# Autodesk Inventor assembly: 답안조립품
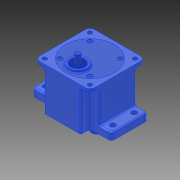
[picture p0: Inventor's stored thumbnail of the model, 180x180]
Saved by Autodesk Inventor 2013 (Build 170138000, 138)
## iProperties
Created: 2015-07
Part Number: 답안조립품
Document SubType Name: Assembly
Designer: user
Author: user
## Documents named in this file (12)
- C:\Users\user\Desktop\450734V1018\답안조립품.iam
- C:\Users\user\Desktop\450734V1018\본체.ipt
- C:\Users\user\Desktop\450734V1018\서브축.ipt
- C:\Users\user\Desktop\450734V1018\베어링 6003.ipt
- 베어링 6003.ipt
- C:\Users\user\Desktop\450734V1018\베어링 608.ipt
- 베어링 608.ipt
- C:\Users\user\Desktop\450734V1018\메인축.ipt
- C:\Users\user\Desktop\450734V1018\오일실 17x32x8.ipt
- C:\Users\user\Desktop\450734V1018\오일실 8x22x7.ipt
- C:\Users\user\Desktop\450734V1018\커버.ipt
- C:\Users\user\Desktop\450734V1018\M4x0.5x16.ipt
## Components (4 placed, 1 different names)
1. M4x0.5x12:1
2. M4x0.5x12:2
3. M4x0.5x12:3
4. M4x0.5x12:4
